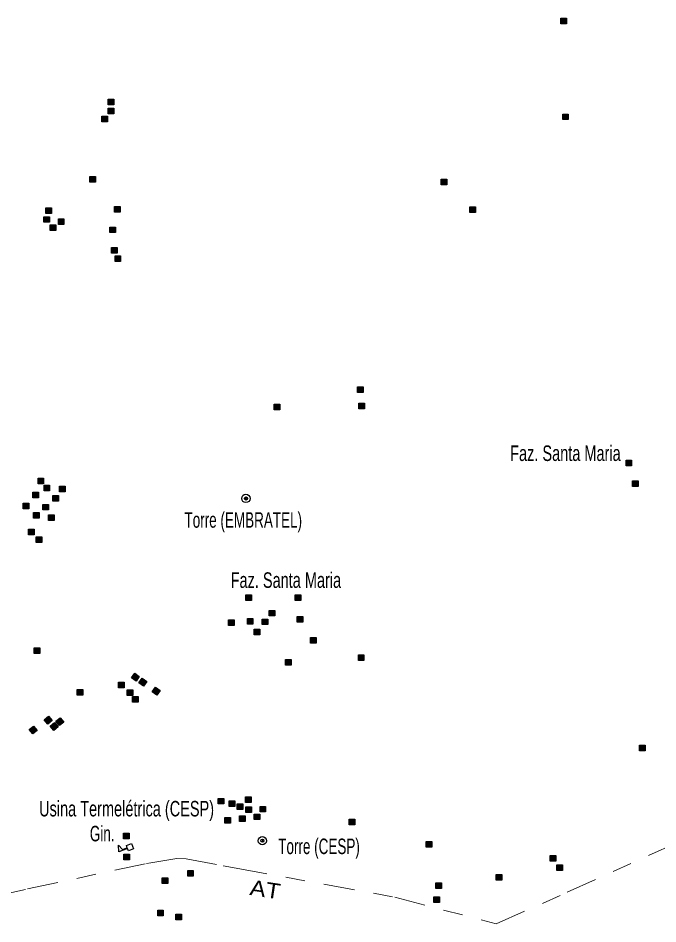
# Model space of a CAD drawing. Extents: x 220.8 to 246.7, y 7287.6 to 7315.8.
# Drawn here: x 233.317 to 236.618, y 7306.501 to 7311.171 of the extents above; entities that cross this region are included whole.
import ezdxf
from ezdxf.enums import TextEntityAlignment as Align

# ---------------------------------------------------------------- set-up
doc = ezdxf.new("R2010")
doc.units = 0
doc.header["$LTSCALE"] = 0.032
doc.header["$PDMODE"] = 32
doc.header["$PDSIZE"] = 0.016
doc.linetypes.add('DOT_DASHED', pattern=[7.7, 5, -1.2, 0.3, -1.2])
for name, color, linetype, lineweight in [('2', 7, 'Continuous', 25), ('4', 7, 'Continuous', 25), ('47', 7, 'Continuous', 25), ('56', 7, 'DOT_DASHED', 13)]:
    doc.layers.add(name, color=color, linetype=linetype, lineweight=lineweight)
doc.layers.add('61', color=7, linetype='Continuous')

msp = doc.modelspace()

# ---------------------------------------------------------------- hatches: boundary and pattern name
at = {"layer": '2'}
for points in [[(236.1169, 7311.1707), (236.1459, 7311.1707), (236.1459, 7311.1417), (236.1169, 7311.1417)], [(233.7824, 7310.7532), (233.8114, 7310.7532), (233.8114, 7310.7242), (233.7824, 7310.7242)], [(233.7824, 7310.7056), (233.8114, 7310.7056), (233.8114, 7310.6766), (233.7824, 7310.6766)], [(233.7494, 7310.6654), (233.7784, 7310.6654), (233.7784, 7310.6364), (233.7494, 7310.6364)], [(236.1271, 7310.6763), (236.1561, 7310.6763), (236.1561, 7310.6473), (236.1271, 7310.6473)], [(233.6869, 7310.3542), (233.7159, 7310.3542), (233.7159, 7310.3252), (233.6869, 7310.3252)], [(235.5002, 7310.3399), (235.5292, 7310.3399), (235.5292, 7310.3109), (235.5002, 7310.3109)], [(233.4609, 7310.192), (233.4899, 7310.192), (233.4899, 7310.163), (233.4609, 7310.163)], [(233.8146, 7310.1999), (233.8436, 7310.1999), (233.8436, 7310.1709), (233.8146, 7310.1709)], [(235.648, 7310.1972), (235.677, 7310.1972), (235.677, 7310.1682), (235.648, 7310.1682)], [(233.4503, 7310.1468), (233.4793, 7310.1468), (233.4793, 7310.1178), (233.4503, 7310.1178)], [(233.4822, 7310.1042), (233.5112, 7310.1042), (233.5112, 7310.0752), (233.4822, 7310.0752)], [(233.5247, 7310.1361), (233.5537, 7310.1361), (233.5537, 7310.1071), (233.5247, 7310.1071)], [(233.7907, 7310.0936), (233.8197, 7310.0936), (233.8197, 7310.0646), (233.7907, 7310.0646)], [(233.7986, 7309.9872), (233.8276, 7309.9872), (233.8276, 7309.9582), (233.7986, 7309.9582)], [(233.8172, 7309.9447), (233.8462, 7309.9447), (233.8462, 7309.9157), (233.8172, 7309.9157)], [(235.0684, 7309.2699), (235.0974, 7309.2699), (235.0974, 7309.2409), (235.0684, 7309.2409)], [(234.6378, 7309.1803), (234.6668, 7309.1803), (234.6668, 7309.1513), (234.6378, 7309.1513)], [(235.075, 7309.1846), (235.104, 7309.1846), (235.104, 7309.1556), (235.075, 7309.1556)], [(236.4539, 7308.8919), (236.4829, 7308.8919), (236.4829, 7308.8629), (236.4539, 7308.8629)], [(233.4197, 7308.7983), (233.4487, 7308.7983), (233.4487, 7308.7693), (233.4197, 7308.7693)], [(236.4876, 7308.7852), (236.5166, 7308.7852), (236.5166, 7308.7562), (236.4876, 7308.7562)], [(233.4506, 7308.7631), (233.4796, 7308.7631), (233.4796, 7308.7341), (233.4506, 7308.7341)], [(233.5302, 7308.7574), (233.5592, 7308.7574), (233.5592, 7308.7284), (233.5302, 7308.7284)], [(233.3938, 7308.7262), (233.4228, 7308.7262), (233.4228, 7308.6972), (233.3938, 7308.6972)], [(233.4961, 7308.7091), (233.5251, 7308.7091), (233.5251, 7308.6801), (233.4961, 7308.6801)], [(233.3427, 7308.6693), (233.3717, 7308.6693), (233.3717, 7308.6403), (233.3427, 7308.6403)], [(233.445, 7308.6637), (233.474, 7308.6637), (233.474, 7308.6347), (233.445, 7308.6347)], [(233.3967, 7308.621), (233.4257, 7308.621), (233.4257, 7308.592), (233.3967, 7308.592)], [(233.4734, 7308.6097), (233.5024, 7308.6097), (233.5024, 7308.5807), (233.4734, 7308.5807)], [(233.3711, 7308.5358), (233.4001, 7308.5358), (233.4001, 7308.5068), (233.3711, 7308.5068)], [(233.4109, 7308.496), (233.4399, 7308.496), (233.4399, 7308.467), (233.4109, 7308.467)], [(234.4925, 7308.197), (234.5215, 7308.197), (234.5215, 7308.168), (234.4925, 7308.168)], [(234.7465, 7308.197), (234.7755, 7308.197), (234.7755, 7308.168), (234.7465, 7308.168)], [(234.612, 7308.1173), (234.641, 7308.1173), (234.641, 7308.0883), (234.612, 7308.0883)], [(234.7565, 7308.0849), (234.7855, 7308.0849), (234.7855, 7308.0559), (234.7565, 7308.0559)], [(234.4028, 7308.0675), (234.4318, 7308.0675), (234.4318, 7308.0385), (234.4028, 7308.0385)], [(234.4999, 7308.075), (234.5289, 7308.075), (234.5289, 7308.046), (234.4999, 7308.046)], [(234.5772, 7308.0725), (234.6062, 7308.0725), (234.6062, 7308.0435), (234.5772, 7308.0435)], [(234.5348, 7308.0202), (234.5638, 7308.0202), (234.5638, 7307.9912), (234.5348, 7307.9912)], [(234.8262, 7307.9778), (234.8552, 7307.9778), (234.8552, 7307.9488), (234.8262, 7307.9488)], [(233.3998, 7307.9239), (233.4288, 7307.9239), (233.4288, 7307.8949), (233.3998, 7307.8949)], [(234.6967, 7307.8632), (234.7257, 7307.8632), (234.7257, 7307.8342), (234.6967, 7307.8342)], [(235.0728, 7307.8881), (235.1018, 7307.8881), (235.1018, 7307.8591), (235.0728, 7307.8591)], [(233.919, 7307.793), (233.9425, 7307.7761), (233.9255, 7307.7526), (233.902, 7307.7695)], [(233.9569, 7307.7672), (233.9804, 7307.7503), (233.9634, 7307.7268), (233.9399, 7307.7437)], [(233.8346, 7307.7463), (233.8636, 7307.7463), (233.8636, 7307.7173), (233.8346, 7307.7173)], [(234.0261, 7307.721), (234.0496, 7307.7041), (234.0326, 7307.6806), (234.0091, 7307.6975)], [(233.6216, 7307.7091), (233.6506, 7307.7091), (233.6506, 7307.6801), (233.6216, 7307.6801)], [(233.8805, 7307.7072), (233.9095, 7307.7072), (233.9095, 7307.6782), (233.8805, 7307.6782)], [(233.9073, 7307.6736), (233.9363, 7307.6736), (233.9363, 7307.6446), (233.9073, 7307.6446)], [(233.4514, 7307.5534), (233.4738, 7307.5719), (233.4923, 7307.5496), (233.4699, 7307.5311)], [(233.4828, 7307.52), (233.5052, 7307.5385), (233.5237, 7307.5162), (233.5013, 7307.4977)], [(233.512, 7307.5451), (233.5344, 7307.5636), (233.5529, 7307.5413), (233.5305, 7307.5228)], [(233.374, 7307.5022), (233.3964, 7307.5207), (233.4149, 7307.4984), (233.3925, 7307.4799)], [(236.5235, 7307.4223), (236.5525, 7307.4223), (236.5525, 7307.3933), (236.5235, 7307.3933)], [(234.4901, 7307.1555), (234.5191, 7307.1555), (234.5191, 7307.1265), (234.4901, 7307.1265)], [(234.3493, 7307.148), (234.3783, 7307.148), (234.3783, 7307.119), (234.3493, 7307.119)], [(234.4057, 7307.1348), (234.4347, 7307.1348), (234.4347, 7307.1058), (234.4057, 7307.1058)], [(234.447, 7307.1198), (234.476, 7307.1198), (234.476, 7307.0908), (234.447, 7307.0908)], [(234.492, 7307.1048), (234.521, 7307.1048), (234.521, 7307.0758), (234.492, 7307.0758)], [(234.5652, 7307.1067), (234.5942, 7307.1067), (234.5942, 7307.0777), (234.5652, 7307.0777)], [(234.4601, 7307.0578), (234.4891, 7307.0578), (234.4891, 7307.0288), (234.4601, 7307.0288)], [(234.5352, 7307.0672), (234.5642, 7307.0672), (234.5642, 7307.0382), (234.5352, 7307.0382)], [(234.3831, 7307.0485), (234.4121, 7307.0485), (234.4121, 7307.0195), (234.3831, 7307.0195)], [(235.0256, 7307.0405), (235.0546, 7307.0405), (235.0546, 7307.0115), (235.0256, 7307.0115)], [(233.8607, 7306.9676), (233.8897, 7306.9676), (233.8897, 7306.9386), (233.8607, 7306.9386)], [(235.4221, 7306.9254), (235.4511, 7306.9254), (235.4511, 7306.8964), (235.4221, 7306.8964)], [(233.863, 7306.8602), (233.892, 7306.8602), (233.892, 7306.8312), (233.863, 7306.8312)], [(236.0621, 7306.8539), (236.0911, 7306.8539), (236.0911, 7306.8249), (236.0621, 7306.8249)], [(234.192, 7306.7757), (234.221, 7306.7757), (234.221, 7306.7467), (234.192, 7306.7467)], [(236.0966, 7306.8049), (236.1256, 7306.8049), (236.1256, 7306.7759), (236.0966, 7306.7759)], [(234.0606, 7306.7381), (234.0896, 7306.7381), (234.0896, 7306.7091), (234.0606, 7306.7091)], [(235.7842, 7306.7548), (235.8132, 7306.7548), (235.8132, 7306.7258), (235.7842, 7306.7258)], [(235.4732, 7306.7122), (235.5022, 7306.7122), (235.5022, 7306.6832), (235.4732, 7306.6832)], [(235.4626, 7306.6405), (235.4916, 7306.6405), (235.4916, 7306.6115), (235.4626, 7306.6115)], [(234.0373, 7306.5714), (234.0663, 7306.5714), (234.0663, 7306.5424), (234.0373, 7306.5424)], [(234.1306, 7306.5511), (234.1596, 7306.5511), (234.1596, 7306.5221), (234.1306, 7306.5221)]]:
    msp.add_hatch(color=256, dxfattribs=at).paths.add_polyline_path(points)

# ---------------------------------------------------------------- linework, layer by layer
for points in [[(236.1169, 7311.1707), (236.1459, 7311.1707), (236.1459, 7311.1417), (236.1169, 7311.1417)], [(233.7824, 7310.7532), (233.8114, 7310.7532), (233.8114, 7310.7242), (233.7824, 7310.7242)], [(233.7824, 7310.7056), (233.8114, 7310.7056), (233.8114, 7310.6766), (233.7824, 7310.6766)], [(233.7494, 7310.6654), (233.7784, 7310.6654), (233.7784, 7310.6364), (233.7494, 7310.6364)], [(236.1271, 7310.6763), (236.1561, 7310.6763), (236.1561, 7310.6473), (236.1271, 7310.6473)], [(233.6869, 7310.3542), (233.7159, 7310.3542), (233.7159, 7310.3252), (233.6869, 7310.3252)], [(235.5002, 7310.3399), (235.5292, 7310.3399), (235.5292, 7310.3109), (235.5002, 7310.3109)], [(233.4609, 7310.192), (233.4899, 7310.192), (233.4899, 7310.163), (233.4609, 7310.163)], [(233.8146, 7310.1999), (233.8436, 7310.1999), (233.8436, 7310.1709), (233.8146, 7310.1709)], [(235.648, 7310.1972), (235.677, 7310.1972), (235.677, 7310.1682), (235.648, 7310.1682)], [(233.4503, 7310.1468), (233.4793, 7310.1468), (233.4793, 7310.1178), (233.4503, 7310.1178)], [(233.4822, 7310.1042), (233.5112, 7310.1042), (233.5112, 7310.0752), (233.4822, 7310.0752)], [(233.5247, 7310.1361), (233.5537, 7310.1361), (233.5537, 7310.1071), (233.5247, 7310.1071)], [(233.7907, 7310.0936), (233.8197, 7310.0936), (233.8197, 7310.0646), (233.7907, 7310.0646)], [(233.7986, 7309.9872), (233.8276, 7309.9872), (233.8276, 7309.9582), (233.7986, 7309.9582)], [(233.8172, 7309.9447), (233.8462, 7309.9447), (233.8462, 7309.9157), (233.8172, 7309.9157)], [(235.0684, 7309.2699), (235.0974, 7309.2699), (235.0974, 7309.2409), (235.0684, 7309.2409)], [(234.6378, 7309.1803), (234.6668, 7309.1803), (234.6668, 7309.1513), (234.6378, 7309.1513)], [(235.075, 7309.1846), (235.104, 7309.1846), (235.104, 7309.1556), (235.075, 7309.1556)], [(236.4539, 7308.8919), (236.4829, 7308.8919), (236.4829, 7308.8629), (236.4539, 7308.8629)], [(233.4197, 7308.7983), (233.4487, 7308.7983), (233.4487, 7308.7693), (233.4197, 7308.7693)], [(236.4876, 7308.7852), (236.5166, 7308.7852), (236.5166, 7308.7562), (236.4876, 7308.7562)], [(233.4506, 7308.7631), (233.4796, 7308.7631), (233.4796, 7308.7341), (233.4506, 7308.7341)], [(233.5302, 7308.7574), (233.5592, 7308.7574), (233.5592, 7308.7284), (233.5302, 7308.7284)], [(233.3938, 7308.7262), (233.4228, 7308.7262), (233.4228, 7308.6972), (233.3938, 7308.6972)], [(233.4961, 7308.7091), (233.5251, 7308.7091), (233.5251, 7308.6801), (233.4961, 7308.6801)], [(233.3427, 7308.6693), (233.3717, 7308.6693), (233.3717, 7308.6403), (233.3427, 7308.6403)], [(233.445, 7308.6637), (233.474, 7308.6637), (233.474, 7308.6347), (233.445, 7308.6347)], [(233.3967, 7308.621), (233.4257, 7308.621), (233.4257, 7308.592), (233.3967, 7308.592)], [(233.4734, 7308.6097), (233.5024, 7308.6097), (233.5024, 7308.5807), (233.4734, 7308.5807)], [(233.3711, 7308.5358), (233.4001, 7308.5358), (233.4001, 7308.5068), (233.3711, 7308.5068)], [(233.4109, 7308.496), (233.4399, 7308.496), (233.4399, 7308.467), (233.4109, 7308.467)], [(234.4925, 7308.197), (234.5215, 7308.197), (234.5215, 7308.168), (234.4925, 7308.168)], [(234.7465, 7308.197), (234.7755, 7308.197), (234.7755, 7308.168), (234.7465, 7308.168)], [(234.612, 7308.1173), (234.641, 7308.1173), (234.641, 7308.0883), (234.612, 7308.0883)], [(234.7565, 7308.0849), (234.7855, 7308.0849), (234.7855, 7308.0559), (234.7565, 7308.0559)], [(234.4028, 7308.0675), (234.4318, 7308.0675), (234.4318, 7308.0385), (234.4028, 7308.0385)], [(234.4999, 7308.075), (234.5289, 7308.075), (234.5289, 7308.046), (234.4999, 7308.046)], [(234.5772, 7308.0725), (234.6062, 7308.0725), (234.6062, 7308.0435), (234.5772, 7308.0435)], [(234.5348, 7308.0202), (234.5638, 7308.0202), (234.5638, 7307.9912), (234.5348, 7307.9912)], [(234.8262, 7307.9778), (234.8552, 7307.9778), (234.8552, 7307.9488), (234.8262, 7307.9488)], [(233.3998, 7307.9239), (233.4288, 7307.9239), (233.4288, 7307.8949), (233.3998, 7307.8949)], [(234.6967, 7307.8632), (234.7257, 7307.8632), (234.7257, 7307.8342), (234.6967, 7307.8342)], [(235.0728, 7307.8881), (235.1018, 7307.8881), (235.1018, 7307.8591), (235.0728, 7307.8591)], [(233.919, 7307.793), (233.9425, 7307.7761), (233.9255, 7307.7526), (233.902, 7307.7695)], [(233.9569, 7307.7672), (233.9804, 7307.7503), (233.9634, 7307.7268), (233.9399, 7307.7437)], [(233.8346, 7307.7463), (233.8636, 7307.7463), (233.8636, 7307.7173), (233.8346, 7307.7173)], [(234.0261, 7307.721), (234.0496, 7307.7041), (234.0326, 7307.6806), (234.0091, 7307.6975)], [(233.6216, 7307.7091), (233.6506, 7307.7091), (233.6506, 7307.6801), (233.6216, 7307.6801)], [(233.8805, 7307.7072), (233.9095, 7307.7072), (233.9095, 7307.6782), (233.8805, 7307.6782)], [(233.9073, 7307.6736), (233.9363, 7307.6736), (233.9363, 7307.6446), (233.9073, 7307.6446)], [(233.4514, 7307.5534), (233.4738, 7307.5719), (233.4923, 7307.5496), (233.4699, 7307.5311)], [(233.4828, 7307.52), (233.5052, 7307.5385), (233.5237, 7307.5162), (233.5013, 7307.4977)], [(233.512, 7307.5451), (233.5344, 7307.5636), (233.5529, 7307.5413), (233.5305, 7307.5228)], [(233.374, 7307.5022), (233.3964, 7307.5207), (233.4149, 7307.4984), (233.3925, 7307.4799)], [(236.5235, 7307.4223), (236.5525, 7307.4223), (236.5525, 7307.3933), (236.5235, 7307.3933)], [(234.4901, 7307.1555), (234.5191, 7307.1555), (234.5191, 7307.1265), (234.4901, 7307.1265)], [(234.3493, 7307.148), (234.3783, 7307.148), (234.3783, 7307.119), (234.3493, 7307.119)], [(234.4057, 7307.1348), (234.4347, 7307.1348), (234.4347, 7307.1058), (234.4057, 7307.1058)], [(234.447, 7307.1198), (234.476, 7307.1198), (234.476, 7307.0908), (234.447, 7307.0908)], [(234.492, 7307.1048), (234.521, 7307.1048), (234.521, 7307.0758), (234.492, 7307.0758)], [(234.5652, 7307.1067), (234.5942, 7307.1067), (234.5942, 7307.0777), (234.5652, 7307.0777)], [(234.4601, 7307.0578), (234.4891, 7307.0578), (234.4891, 7307.0288), (234.4601, 7307.0288)], [(234.5352, 7307.0672), (234.5642, 7307.0672), (234.5642, 7307.0382), (234.5352, 7307.0382)], [(234.3831, 7307.0485), (234.4121, 7307.0485), (234.4121, 7307.0195), (234.3831, 7307.0195)], [(235.0256, 7307.0405), (235.0546, 7307.0405), (235.0546, 7307.0115), (235.0256, 7307.0115)], [(233.8607, 7306.9676), (233.8897, 7306.9676), (233.8897, 7306.9386), (233.8607, 7306.9386)], [(235.4221, 7306.9254), (235.4511, 7306.9254), (235.4511, 7306.8964), (235.4221, 7306.8964)], [(233.863, 7306.8602), (233.892, 7306.8602), (233.892, 7306.8312), (233.863, 7306.8312)], [(236.0621, 7306.8539), (236.0911, 7306.8539), (236.0911, 7306.8249), (236.0621, 7306.8249)], [(234.192, 7306.7757), (234.221, 7306.7757), (234.221, 7306.7467), (234.192, 7306.7467)], [(236.0966, 7306.8049), (236.1256, 7306.8049), (236.1256, 7306.7759), (236.0966, 7306.7759)], [(234.0606, 7306.7381), (234.0896, 7306.7381), (234.0896, 7306.7091), (234.0606, 7306.7091)], [(235.7842, 7306.7548), (235.8132, 7306.7548), (235.8132, 7306.7258), (235.7842, 7306.7258)], [(235.4732, 7306.7122), (235.5022, 7306.7122), (235.5022, 7306.6832), (235.4732, 7306.6832)], [(235.4626, 7306.6405), (235.4916, 7306.6405), (235.4916, 7306.6115), (235.4626, 7306.6115)], [(234.0373, 7306.5714), (234.0663, 7306.5714), (234.0663, 7306.5424), (234.0373, 7306.5424)], [(234.1306, 7306.5511), (234.1596, 7306.5511), (234.1596, 7306.5221), (234.1306, 7306.5221)]]:
    msp.add_lwpolyline(points, close=True, dxfattribs=at)
at = {"layer": '4'}
for points in [[(233.8817, 7306.8889), (233.8366, 7306.8714), (233.8352, 7306.9072), (233.8556, 7306.884), (233.88, 7306.8934)], [(233.88, 7306.8934), (233.8756, 7306.9047), (233.9027, 7306.9152), (233.9131, 7306.8881), (233.8861, 7306.8777), (233.8817, 7306.8889)]]:
    msp.add_lwpolyline(points, dxfattribs=at)
at = {"layer": '47'}
for centre in [(234.4924, 7308.6942), (234.5773, 7306.9295)]:
    msp.add_circle(centre, 0.0215, dxfattribs=at)
for p in [(234.4926, 7308.6941), (234.5775, 7306.9294)]:
    msp.add_point(p, dxfattribs=at)
at = {"layer": '56'}
for points in [[(233.3657, 7306.6808), (233.9802, 7306.8124), (234.0015, 7306.8162), (234.1355, 7306.8375), (234.184, 7306.8362), (234.3746, 7306.8002), (234.4423, 7306.7876), (235.2612, 7306.6381), (235.7845, 7306.5007), (236.1507, 7306.6634), (236.9321, 7307.0166), (237.442, 7306.9659), (238.2941, 7306.8672), (238.3461, 7306.8646), (238.7464, 7306.9763), (238.8939, 7307.0343), (239.3316, 7307.1323), (239.6224, 7307.1942), (239.7076, 7307.1857), (239.9155, 7307.2208)], [(233.1986, 7306.6434), (233.3657, 7306.6808)]]:
    msp.add_lwpolyline(points, dxfattribs=at)

# ---------------------------------------------------------------- texts
at = {"layer": '61'}
for s, width, p in [('Faz. Santa Maria', 0.7, (236.4263, 7308.8873)), ('Torre (EMBRATEL)', 0.65, (234.7822, 7308.5434)), ('Faz. Santa Maria', 0.7, (234.9839, 7308.2332)), ('Usina Termelétrica (CESP)', 0.7, (234.3282, 7307.0547)), ('Gin.', 0.65, (233.8147, 7306.9262))]:
    msp.add_text(s, height=0.08, dxfattribs=dict(at, width=width)).set_placement(p, align=Align.RIGHT)
at = {"layer": '61', "width": 0.65}
msp.add_text('Torre (CESP)', height=0.08, dxfattribs=at).set_placement((234.6593, 7306.8605))
at = {"layer": '61', "width": 1.15}
msp.add_text('AT', height=0.08, rotation=351.449, dxfattribs=at).set_placement((234.5862, 7306.6385), align=Align.CENTER)

doc.saveas('drawing.dxf')
